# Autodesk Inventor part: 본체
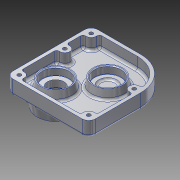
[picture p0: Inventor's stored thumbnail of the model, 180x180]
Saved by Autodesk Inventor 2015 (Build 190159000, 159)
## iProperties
Created: 2015-10
Part Number: 본체
Material: Aluminum 6061
Document SubType Name: Modeling
Designer: youjin20
Density: 2.7 g/cm^3
Appearance: Aluminum - Flat
Mass: 246.639 g
Surface Area: 389.424 cm^2
Volume: 91.3479 cm^3
Author: youjin20
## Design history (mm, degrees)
sketch "Sketch1"
  geometry: L1 (-22, 73)-(30, 73); L2 (70, 33)-(70, -22); L3 (62, -30)-(-22, -30); L4 (-30, -22)-(-30, 65); A1 r 8 centre (-22, 65) between (-22, 73) and (-30, 65); A2 r 8 centre (62, -22) between (62, -30) and (70, -22); A3 r 8 centre (-22, -22) between (-30, -22) and (-22, -30); A4 r 40 centre (30, 33) between (70, 33) and (30, 73); 4 further points
  constraints: 8 end point, 8 point on circle, 8 tangent, 6 point on line, 4 centre point, 2 equal radius, 2 parallel, 1 horizontal, 1 perpendicular
  dimensions: "d0" = 100 distance of point (70, -30) point (-30, -30); "d1" = 103 distance of point (-30, -30) point (-30, 73); "d2" = 30 distance from line of L3 point (0, 0); "d3" = 30 distance from line of L4 point (0, 0); "d4" = 8 radius of A1; "d5" = 40 radius of A4
extrude "Extrusion1" new body sketch "Sketch1" distance "d6" = 18; taper "d7" = 0 deg
shell "Shell1" dims "d8" = 4
sketch "Sketch2"
  geometry: C1 r 25 at (0, 0); 1 further point
  constraints: 1 centre point, 1 coincident
  dimensions: "d9" = 50 diameter of C1
extrude "Extrusion2" join sketch "Sketch2" distance "d10" = 15; taper "d11" = -10 deg
hole "Hole1" diameter "d14" = 24; stored, may be unused: countersink angle "d18" = 90 deg, drill point angle "d20" = 0 deg; dims "d15" = 6, "d16" = 28, "d17" = 11, "d19" = 13, "d21" = 10, "d22" = 10
sketch "Sketch3"
  geometry: C1 r 20 at (22, 26); 1 further point
  constraints: 1 centre point, 1 coincident
  dimensions: "d23" = 40 diameter of C1
extrude "Extrusion3" join sketch "Sketch3" distance "d24" = 11; taper "d25" = -10 deg
sketch "Sketch4"
  geometry: C1 r 10 at (0, 0); 1 further point
  constraints: 1 centre point, 1 coincident
  dimensions: "d26" = 20 diameter of C1
extrude "Extrusion4" cut sketch "Sketch4" distance "d27" = 8; taper "d28" = 0 deg
sketch "Sketch5"
  geometry: C1 r 16 at (0, 0); 1 further point
  constraints: 1 centre point, 1 coincident
  dimensions: "d29" = 32 diameter of C1
extrude "Extrusion5" cut sketch "Sketch5" distance "d30" = 11; taper "d31" = 0 deg
chamfer "Chamfer1" distance "d32" = 1; stored, may be unused: second distance "d33" = 2, angle "d34" = 45 deg
chamfer "Chamfer2" distance "d35" = 1; stored, may be unused: second distance "d36" = 2, angle "d37" = 45 deg
fillet "Fillet1" dims "d38" = 0.3
fillet "Fillet2" dims "d39" = 0.3
fillet "Fillet3" dims "d40" = 3
sketch "Sketch6"
  geometry: C1 r 20 at (52, 59); A1 r 40 centre (52, 59) between (92, 59) and (52, 99) reference; A2 r 36 centre (52, 59) between (88, 59) and (52, 95) reference; 1 further point
  constraints: 1 centre point, 1 coincident
  dimensions: "d44" = 40 diameter of C1
extrude "Extrusion6" join sketch "Sketch6" distance "d45" = 11; taper "d46" = -10 deg
hole "Hole2" diameter "d49" = 22; stored, may be unused: countersink angle "d53" = 90 deg, drill point angle "d55" = 0 deg; dims "d50" = 6, "d51" = 32, "d52" = 9, "d54" = 11, "d56" = 10, "d57" = 10
fillet "Fillet4" dims "d58" = 0.3
fillet "Fillet5" dims "d59" = 3
sketch "Sketch7"
  geometry: L1 (92, 4)-(92, 59) reference; L2 (0, -4)-(84, -4) reference; C1 r 6 at (0, 91); C2 r 6 at (0, 59); C3 r 6 at (0, 4); C4 r 6 at (84, 4); C5 r 6 at (84, 59); C6 r 8.172 at (52, 59) reference; 1 further point
  constraints: 5 centre point, 2 horizontal alignment, 2 vertical alignment
  dimensions: "d60" = 6 radius of C1; "d61" = 6 radius of C2; "d62" = 6 radius of C3; "d63" = 6 radius of C4; "d64" = 6 radius of C5; "d65" = 84 horizontal distance of C5.centre C1.centre; "d66" = 32 vertical distance of C6.centre C1.centre; "d67" = 55 distance of C4.centre C5.centre; "d68" = 8 distance from line of L1 C4.centre; "d69" = 8 distance from line of L1 C5.centre; "d70" = 8 distance from line of L2 C3.centre
extrude "Extrusion7" join sketch "Sketch7" distance "d71" = 14; taper "d72" = 0 deg
fillet "Fillet6" dims "d80" = 3
fillet "Fillet7" dims "d81" = 3
fillet "Fillet8" dims "d82" = 3
sketch "Sketch9"
  geometry: L1 (30, 65)-(30, -22) reference; L2 (22, -30)-(-62, -30) reference; L3 (-70, -22)-(-70, 33) reference; L4 (-30, 73)-(22, 73) reference; L5 (26, -13.056)-(26, 24.056) reference; L6 (26, 41.944)-(26, 56.056) reference; L7 (13.056, 69)-(-30, 69) reference; L8 (-66, 24.056)-(-66, -13.056) reference; L9 (-53.056, -26)-(13.056, -26) reference; A1 r 8 centre (22, -22) between (22, -30) and (30, -22) reference; A2 r 8 centre (-62, -22) between (-70, -22) and (-62, -30) reference; A3 r 40 centre (-30, 33) between (-30, 73) and (-70, 33) reference; A4 r 8 centre (22, 65) between (30, 65) and (22, 73) reference; A5 r 6 centre (22, -22) between (22.667, -16.037) and (16.037, -22.667) reference; A6 r 3 centre (23, -13.056) between (22.667, -16.037) and (26, -13.056) reference; A7 r 3 centre (23, 24.056) between (26, 24.056) and (22.667, 27.037) reference; A8 r 6 centre (22, 33) between (22.667, 38.963) and (22.667, 27.037) reference; A9 r 3 centre (23, 41.944) between (22.667, 38.963) and (26, 41.944) reference; A10 r 3 centre (23, 56.056) between (26, 56.056) and (22.667, 59.037) reference; A11 r 6 centre (22, 65) between (16.037, 65.667) and (22.667, 59.037) reference; A12 r 3 centre (13.056, 66) between (16.037, 65.667) and (13.056, 69) reference; A13 r 36 centre (-30, 33) between (-30, 69) and (-64.636, 42.814) reference; A14 r 3 centre (-61.75, 41.997) between (-64.636, 42.814) and (-61.833, 38.998) reference; A15 r 6 centre (-62, 33) between (-62.667, 27.037) and (-61.833, 38.998) reference; A16 r 3 centre (-63, 24.056) between (-62.667, 27.037) and (-66, 24.056) reference; A17 r 3 centre (-63, -13.056) between (-66, -13.056) and (-62.667, -16.037) reference; A18 r 6 centre (-62, -22) between (-56.037, -22.667) and (-62.667, -16.037) reference; A19 r 3 centre (-53.056, -23) between (-56.037, -22.667) and (-53.056, -26) reference; A20 r 3 centre (13.056, -23) between (13.056, -26) and (16.037, -22.667) reference; 6 further points
  constraints: 5 coincident
hole "Hole4" sketch "Sketch9" at (22, 65), (-62, 33), (-62, -22), (22, -22), (22, 33) diameter "d83" = 4.5; stored, may be unused: countersink angle "d87" = 90 deg, drill point angle "d89" = 0 deg; dims "d84" = 6, "d85" = 8, "d86" = 4.4, "d88" = 18
fillet "Fillet9" dims "d90" = 3
fillet "Fillet10" dims "d91" = 3
sketch "Sketch10"
  geometry: L1 (30, 5.311)-(30, 65) reference; L2 (22, 73)-(-30, 73) reference; 2 further points
  constraints: 1 other
  dimensions: "d92" = 40 distance from line of L1 point (-10, 53); "d93" = 20 distance from line of L2 point (-10, 53)
emboss "Emboss1" sketch "Sketch10" dims "d0" = 100, "d1" = 103, "d2" = 30, "d3" = 30, "d4" = 8, "d5" = 40, "d94" = 0.5, "d95" = 0
sketch "Sketch11"
  geometry: A1 r 18 centre (0, 0) between (0, 18) and (18, 0); 3 further points
  constraints: 4 point on circle, 2 horizontal alignment, 2 vertical alignment, 1 centre point, 1 coincident
  dimensions: "d96" = 36 diameter of A1
hole "Hole5" sketch "Sketch11" at (0, 18), (18, 0), (-18, 0), (0, -18) diameter "d97" = 2.459; stored, may be unused: countersink angle "d101" = 90 deg, drill point angle "d103" = 118 deg; dims "d98" = 8, "d99" = 8, "d100" = 4.4, "d102" = 10
chamfer "Chamfer3" distance "d104" = 1; stored, may be unused: second distance "d105" = 2, angle "d106" = 45 deg
body "Solid1"
node "Projected Loop1"
node "Projected Loop3"
